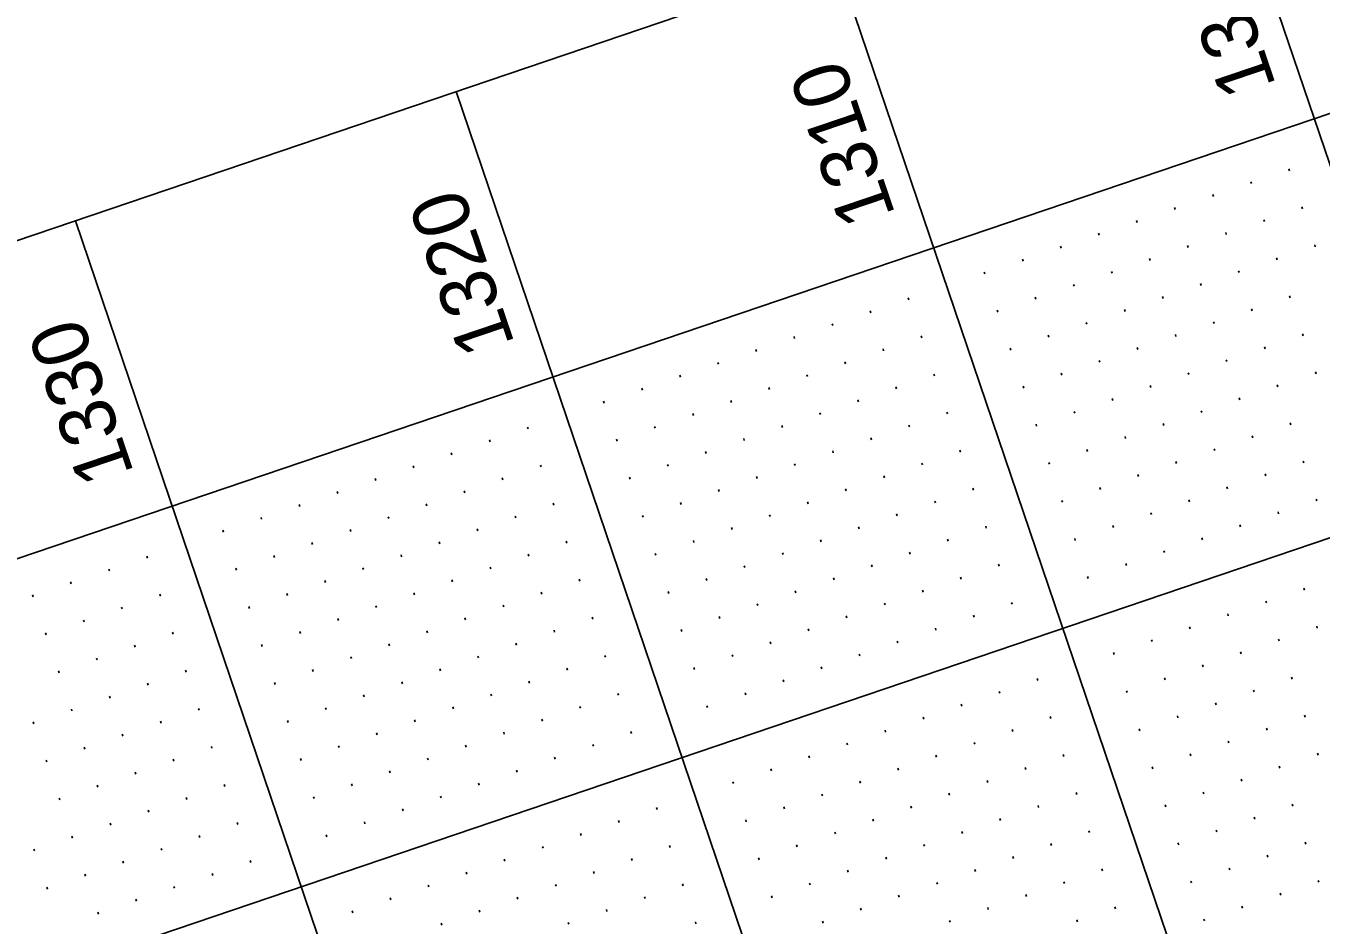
# Model space of a CAD drawing. Extents: x 2150800 to 2152547, y 141860 to 143950.
# Drawn here: x 2151517.9 to 2151679, y 143674.4 to 143786.3 of the extents above; entities that cross this region are included whole.
import ezdxf

# ---------------------------------------------------------------- set-up
doc = ezdxf.new("R2010")
doc.units = 0
for name, color, linetype in [('SHT_Plan_Profile_Sheet_Elev_Txt', 7, 'Continuous'), ('SHT_Profile_Grid_Major', 7, 'Continuous'), ('SHT_Profile_Grid_Minor', 7, 'Continuous'), ('SHT_Sheet_Border', 7, 'Continuous')]:
    doc.layers.add(name, color=color, linetype=linetype)

msp = doc.modelspace()

# ---------------------------------------------------------------- linework, layer by layer
at = {"layer": 'SHT_Profile_Grid_Major'}
for p, q in [((2152172.11, 142318.73), (2151666.12, 143810.24)), ((2152124.76, 142302.67), (2151618.77, 143794.18)), ((2152077.41, 142286.61), (2151571.42, 143778.12)), ((2152030.06, 142270.54), (2151524.07, 143762.05)), ((2151788.93, 143759.51), (2151452.75, 143645.46))]:
    msp.add_line(p, q, dxfattribs=at)
at = {"layer": 'SHT_Profile_Grid_Minor'}
for p, q in [((2151675.08, 143768.27), (2151675, 143768.51)), ((2151670.34, 143766.66), (2151670.26, 143766.9)), ((2151665.61, 143765.06), (2151665.53, 143765.29)), ((2151660.87, 143763.45), (2151660.79, 143763.69)), ((2151676.69, 143763.54), (2151676.61, 143763.77)), ((2151656.14, 143761.84), (2151656.06, 143762.08)), ((2151671.95, 143761.93), (2151671.87, 143762.17)), ((2151651.41, 143760.24), (2151651.32, 143760.48)), ((2151667.22, 143760.32), (2151667.14, 143760.56)), ((2151646.67, 143758.63), (2151646.59, 143758.87)), ((2151662.48, 143758.72), (2151662.4, 143758.95)), ((2151678.29, 143758.8), (2151678.21, 143759.04)), ((2151641.94, 143757.03), (2151641.85, 143757.26)), ((2151657.75, 143757.11), (2151657.67, 143757.35)), ((2151673.56, 143757.19), (2151673.48, 143757.43)), ((2151637.2, 143755.42), (2151637.12, 143755.66)), ((2151653.01, 143755.5), (2151652.93, 143755.74)), ((2151668.82, 143755.59), (2151668.74, 143755.82)), ((2151648.28, 143753.9), (2151648.2, 143754.13)), ((2151664.09, 143753.98), (2151664.01, 143754.22)), ((2151627.73, 143752.21), (2151627.65, 143752.44)), ((2151643.54, 143752.29), (2151643.46, 143752.53)), ((2151659.35, 143752.38), (2151659.27, 143752.61)), ((2151675.16, 143752.46), (2151675.08, 143752.7)), ((2151623, 143750.6), (2151622.92, 143750.84)), ((2151638.81, 143750.68), (2151638.73, 143750.92)), ((2151654.62, 143750.77), (2151654.54, 143751.01)), ((2151670.43, 143750.85), (2151670.35, 143751.09)), ((2151618.26, 143748.99), (2151618.18, 143749.23)), ((2151649.88, 143749.16), (2151649.8, 143749.4)), ((2151665.69, 143749.25), (2151665.61, 143749.48)), ((2151613.53, 143747.39), (2151613.45, 143747.62)), ((2151629.34, 143747.47), (2151629.26, 143747.71)), ((2151645.15, 143747.56), (2151645.07, 143747.79)), ((2151660.96, 143747.64), (2151660.88, 143747.88)), ((2151676.77, 143747.72), (2151676.69, 143747.96)), ((2151608.79, 143745.78), (2151608.71, 143746.02)), ((2151624.6, 143745.87), (2151624.52, 143746.1)), ((2151640.41, 143745.95), (2151640.33, 143746.19)), ((2151656.22, 143746.03), (2151656.14, 143746.27)), ((2151672.04, 143746.12), (2151671.95, 143746.35)), ((2151604.06, 143744.18), (2151603.98, 143744.41)), ((2151619.87, 143744.26), (2151619.79, 143744.5)), ((2151651.49, 143744.43), (2151651.41, 143744.66)), ((2151667.3, 143744.51), (2151667.22, 143744.75)), ((2151599.32, 143742.57), (2151599.24, 143742.81)), ((2151615.13, 143742.65), (2151615.05, 143742.89)), ((2151630.94, 143742.74), (2151630.86, 143742.97)), ((2151646.75, 143742.82), (2151646.67, 143743.06)), ((2151662.57, 143742.91), (2151662.48, 143743.14)), ((2151678.38, 143742.99), (2151678.3, 143743.23)), ((2151594.59, 143740.96), (2151594.51, 143741.2)), ((2151610.4, 143741.05), (2151610.32, 143741.28)), ((2151626.21, 143741.13), (2151626.13, 143741.37)), ((2151642.02, 143741.21), (2151641.94, 143741.45)), ((2151657.83, 143741.3), (2151657.75, 143741.54)), ((2151673.64, 143741.38), (2151673.56, 143741.62)), ((2151589.85, 143739.36), (2151589.77, 143739.59)), ((2151605.66, 143739.44), (2151605.58, 143739.68)), ((2151621.47, 143739.52), (2151621.39, 143739.76)), ((2151653.1, 143739.69), (2151653.02, 143739.93)), ((2151668.91, 143739.78), (2151668.83, 143740.01)), ((2151600.93, 143737.83), (2151600.85, 143738.07)), ((2151616.74, 143737.92), (2151616.66, 143738.15)), ((2151632.55, 143738), (2151632.47, 143738.24)), ((2151648.36, 143738.09), (2151648.28, 143738.32)), ((2151664.17, 143738.17), (2151664.09, 143738.41)), ((2151580.38, 143736.14), (2151580.3, 143736.38)), ((2151596.19, 143736.23), (2151596.11, 143736.46)), ((2151612, 143736.31), (2151611.92, 143736.55)), ((2151627.81, 143736.4), (2151627.73, 143736.63)), ((2151643.63, 143736.48), (2151643.55, 143736.72)), ((2151659.44, 143736.56), (2151659.36, 143736.8)), ((2151675.25, 143736.65), (2151675.17, 143736.88)), ((2151575.65, 143734.54), (2151575.57, 143734.77)), ((2151591.46, 143734.62), (2151591.38, 143734.86)), ((2151607.27, 143734.71), (2151607.19, 143734.94)), ((2151623.08, 143734.79), (2151623, 143735.03)), ((2151654.7, 143734.96), (2151654.62, 143735.19)), ((2151670.51, 143735.04), (2151670.43, 143735.28)), ((2151570.91, 143732.93), (2151570.83, 143733.17)), ((2151602.53, 143733.1), (2151602.45, 143733.34)), ((2151618.34, 143733.18), (2151618.26, 143733.42)), ((2151634.16, 143733.27), (2151634.08, 143733.5)), ((2151649.97, 143733.35), (2151649.89, 143733.59)), ((2151665.78, 143733.44), (2151665.7, 143733.67)), ((2151566.18, 143731.32), (2151566.1, 143731.56)), ((2151581.99, 143731.41), (2151581.91, 143731.65)), ((2151597.8, 143731.49), (2151597.72, 143731.73)), ((2151613.61, 143731.58), (2151613.53, 143731.81)), ((2151629.42, 143731.66), (2151629.34, 143731.9)), ((2151645.23, 143731.74), (2151645.15, 143731.98)), ((2151661.04, 143731.83), (2151660.96, 143732.07)), ((2151676.85, 143731.91), (2151676.77, 143732.15)), ((2151561.44, 143729.72), (2151561.36, 143729.96)), ((2151577.25, 143729.8), (2151577.17, 143730.04)), ((2151593.06, 143729.89), (2151592.98, 143730.12)), ((2151608.87, 143729.97), (2151608.79, 143730.21)), ((2151624.69, 143730.05), (2151624.61, 143730.29)), ((2151656.31, 143730.22), (2151656.23, 143730.46)), ((2151672.12, 143730.31), (2151672.04, 143730.54)), ((2151556.71, 143728.11), (2151556.63, 143728.35)), ((2151572.52, 143728.2), (2151572.44, 143728.43)), ((2151604.14, 143728.36), (2151604.06, 143728.6)), ((2151619.95, 143728.45), (2151619.87, 143728.69)), ((2151635.76, 143728.53), (2151635.68, 143728.77)), ((2151651.57, 143728.62), (2151651.49, 143728.85)), ((2151667.38, 143728.7), (2151667.3, 143728.94)), ((2151551.97, 143726.51), (2151551.89, 143726.74)), ((2151567.78, 143726.59), (2151567.7, 143726.83)), ((2151583.59, 143726.67), (2151583.51, 143726.91)), ((2151599.4, 143726.76), (2151599.32, 143726.99)), ((2151615.22, 143726.84), (2151615.14, 143727.08)), ((2151631.03, 143726.93), (2151630.95, 143727.16)), ((2151646.84, 143727.01), (2151646.76, 143727.25)), ((2151662.65, 143727.09), (2151662.57, 143727.33)), ((2151678.46, 143727.18), (2151678.38, 143727.41)), ((2151547.24, 143724.9), (2151547.16, 143725.14)), ((2151563.05, 143724.98), (2151562.97, 143725.22)), ((2151578.86, 143725.07), (2151578.78, 143725.3)), ((2151594.67, 143725.15), (2151594.59, 143725.39)), ((2151610.48, 143725.24), (2151610.4, 143725.47)), ((2151626.29, 143725.32), (2151626.21, 143725.56)), ((2151657.91, 143725.49), (2151657.83, 143725.72)), ((2151673.73, 143725.57), (2151673.65, 143725.81)), ((2151542.5, 143723.29), (2151542.42, 143723.53)), ((2151558.31, 143723.38), (2151558.23, 143723.61)), ((2151574.12, 143723.46), (2151574.04, 143723.7)), ((2151605.75, 143723.63), (2151605.67, 143723.87)), ((2151621.56, 143723.71), (2151621.48, 143723.95)), ((2151637.37, 143723.8), (2151637.29, 143724.03)), ((2151653.18, 143723.88), (2151653.1, 143724.12)), ((2151668.99, 143723.97), (2151668.91, 143724.2)), ((2151553.58, 143721.77), (2151553.5, 143722.01)), ((2151569.39, 143721.86), (2151569.31, 143722.09)), ((2151585.2, 143721.94), (2151585.12, 143722.18)), ((2151601.01, 143722.02), (2151600.93, 143722.26)), ((2151616.82, 143722.11), (2151616.74, 143722.34)), ((2151632.63, 143722.19), (2151632.55, 143722.43)), ((2151648.44, 143722.28), (2151648.36, 143722.51)), ((2151664.26, 143722.36), (2151664.18, 143722.6)), ((2151533.03, 143720.08), (2151532.95, 143720.32)), ((2151548.84, 143720.16), (2151548.76, 143720.4)), ((2151564.65, 143720.25), (2151564.57, 143720.49)), ((2151580.46, 143720.33), (2151580.38, 143720.57)), ((2151596.28, 143720.42), (2151596.2, 143720.65)), ((2151612.09, 143720.5), (2151612.01, 143720.74)), ((2151627.9, 143720.58), (2151627.82, 143720.82)), ((2151659.52, 143720.75), (2151659.44, 143720.99)), ((2151528.3, 143718.47), (2151528.22, 143718.71)), ((2151544.11, 143718.56), (2151544.03, 143718.8)), ((2151559.92, 143718.64), (2151559.84, 143718.88)), ((2151575.73, 143718.73), (2151575.65, 143718.96)), ((2151607.35, 143718.89), (2151607.27, 143719.13)), ((2151623.16, 143718.98), (2151623.08, 143719.22)), ((2151638.97, 143719.06), (2151638.89, 143719.3)), ((2151654.79, 143719.15), (2151654.71, 143719.38)), ((2151523.56, 143716.87), (2151523.48, 143717.1)), ((2151555.18, 143717.04), (2151555.1, 143717.27)), ((2151570.99, 143717.12), (2151570.91, 143717.36)), ((2151586.81, 143717.2), (2151586.73, 143717.44)), ((2151602.62, 143717.29), (2151602.54, 143717.52)), ((2151618.43, 143717.37), (2151618.35, 143717.61)), ((2151634.24, 143717.46), (2151634.16, 143717.69)), ((2151650.05, 143717.54), (2151649.97, 143717.78)), ((2151676.94, 143716.1), (2151676.86, 143716.34)), ((2151518.83, 143715.26), (2151518.75, 143715.5)), ((2151534.64, 143715.35), (2151534.56, 143715.58)), ((2151550.45, 143715.43), (2151550.37, 143715.67)), ((2151566.26, 143715.51), (2151566.18, 143715.75)), ((2151582.07, 143715.6), (2151581.99, 143715.83)), ((2151597.88, 143715.68), (2151597.8, 143715.92)), ((2151613.69, 143715.77), (2151613.61, 143716)), ((2151629.5, 143715.85), (2151629.42, 143716.09)), ((2151672.2, 143714.5), (2151672.12, 143714.73)), ((2151529.9, 143713.74), (2151529.82, 143713.98)), ((2151545.71, 143713.82), (2151545.63, 143714.06)), ((2151561.53, 143713.91), (2151561.44, 143714.14)), ((2151577.34, 143713.99), (2151577.26, 143714.23)), ((2151608.96, 143714.16), (2151608.88, 143714.4)), ((2151624.77, 143714.24), (2151624.69, 143714.48)), ((2151640.58, 143714.33), (2151640.5, 143714.56)), ((2151667.47, 143712.89), (2151667.39, 143713.13)), ((2151525.17, 143712.13), (2151525.09, 143712.37)), ((2151556.79, 143712.3), (2151556.71, 143712.54)), ((2151572.6, 143712.39), (2151572.52, 143712.62)), ((2151588.41, 143712.47), (2151588.33, 143712.71)), ((2151604.22, 143712.55), (2151604.14, 143712.79)), ((2151620.03, 143712.64), (2151619.95, 143712.87)), ((2151635.85, 143712.72), (2151635.77, 143712.96)), ((2151662.73, 143711.28), (2151662.65, 143711.52)), ((2151678.54, 143711.37), (2151678.46, 143711.6)), ((2151520.43, 143710.53), (2151520.35, 143710.76)), ((2151536.24, 143710.61), (2151536.16, 143710.85)), ((2151552.06, 143710.69), (2151551.97, 143710.93)), ((2151567.87, 143710.78), (2151567.79, 143711.02)), ((2151583.68, 143710.86), (2151583.6, 143711.1)), ((2151599.49, 143710.95), (2151599.41, 143711.18)), ((2151615.3, 143711.03), (2151615.22, 143711.27)), ((2151631.11, 143711.11), (2151631.03, 143711.35)), ((2151658, 143709.68), (2151657.92, 143709.91)), ((2151673.81, 143709.76), (2151673.73, 143710)), ((2151531.51, 143709), (2151531.43, 143709.24)), ((2151547.32, 143709.09), (2151547.24, 143709.33)), ((2151563.13, 143709.17), (2151563.05, 143709.41)), ((2151578.94, 143709.26), (2151578.86, 143709.49)), ((2151610.56, 143709.42), (2151610.48, 143709.66)), ((2151626.38, 143709.51), (2151626.3, 143709.75)), ((2151653.26, 143708.07), (2151653.18, 143708.31)), ((2151669.07, 143708.15), (2151668.99, 143708.39)), ((2151526.77, 143707.4), (2151526.69, 143707.63)), ((2151558.4, 143707.57), (2151558.32, 143707.8)), ((2151574.21, 143707.65), (2151574.13, 143707.89)), ((2151590.02, 143707.73), (2151589.94, 143707.97)), ((2151605.83, 143707.82), (2151605.75, 143708.05)), ((2151621.64, 143707.9), (2151621.56, 143708.14)), ((2151664.34, 143706.55), (2151664.26, 143706.78)), ((2151522.04, 143705.79), (2151521.96, 143706.03)), ((2151537.85, 143705.88), (2151537.77, 143706.11)), ((2151553.66, 143705.96), (2151553.58, 143706.2)), ((2151569.47, 143706.04), (2151569.39, 143706.28)), ((2151585.28, 143706.13), (2151585.2, 143706.36)), ((2151601.09, 143706.21), (2151601.01, 143706.45)), ((2151616.91, 143706.3), (2151616.83, 143706.53)), ((2151643.79, 143704.86), (2151643.71, 143705.09)), ((2151659.6, 143704.94), (2151659.52, 143705.18)), ((2151675.42, 143705.03), (2151675.34, 143705.26)), ((2151533.12, 143704.27), (2151533.03, 143704.51)), ((2151548.93, 143704.35), (2151548.85, 143704.59)), ((2151564.74, 143704.44), (2151564.66, 143704.67)), ((2151580.55, 143704.52), (2151580.47, 143704.76)), ((2151612.17, 143704.69), (2151612.09, 143704.93)), ((2151639.06, 143703.25), (2151638.98, 143703.49)), ((2151654.87, 143703.34), (2151654.79, 143703.57)), ((2151670.68, 143703.42), (2151670.6, 143703.66)), ((2151528.38, 143702.66), (2151528.3, 143702.9)), ((2151560, 143702.83), (2151559.92, 143703.07)), ((2151575.81, 143702.92), (2151575.73, 143703.15)), ((2151591.63, 143703), (2151591.54, 143703.24)), ((2151607.44, 143703.08), (2151607.36, 143703.32)), ((2151634.32, 143701.64), (2151634.24, 143701.88)), ((2151665.95, 143701.81), (2151665.87, 143702.05)), ((2151523.65, 143701.06), (2151523.57, 143701.29)), ((2151539.46, 143701.14), (2151539.38, 143701.38)), ((2151555.27, 143701.22), (2151555.19, 143701.46)), ((2151571.08, 143701.31), (2151571, 143701.55)), ((2151586.89, 143701.39), (2151586.81, 143701.63)), ((2151602.7, 143701.48), (2151602.62, 143701.71)), ((2151629.59, 143700.04), (2151629.51, 143700.28)), ((2151645.4, 143700.12), (2151645.32, 143700.36)), ((2151661.21, 143700.21), (2151661.13, 143700.44)), ((2151677.02, 143700.29), (2151676.94, 143700.53)), ((2151518.91, 143699.45), (2151518.83, 143699.69)), ((2151534.72, 143699.53), (2151534.64, 143699.77)), ((2151550.53, 143699.62), (2151550.45, 143699.86)), ((2151566.34, 143699.7), (2151566.26, 143699.94)), ((2151582.16, 143699.79), (2151582.07, 143700.02)), ((2151624.85, 143698.43), (2151624.77, 143698.67)), ((2151640.66, 143698.52), (2151640.58, 143698.75)), ((2151656.48, 143698.6), (2151656.4, 143698.84)), ((2151672.29, 143698.68), (2151672.21, 143698.92)), ((2151529.99, 143697.93), (2151529.91, 143698.17)), ((2151561.61, 143698.1), (2151561.53, 143698.33)), ((2151577.42, 143698.18), (2151577.34, 143698.42)), ((2151593.23, 143698.26), (2151593.15, 143698.5)), ((2151620.12, 143696.83), (2151620.04, 143697.06)), ((2151635.93, 143696.91), (2151635.85, 143697.15)), ((2151667.55, 143697.08), (2151667.47, 143697.31)), ((2151525.25, 143696.32), (2151525.17, 143696.56)), ((2151541.06, 143696.41), (2151540.98, 143696.64)), ((2151556.87, 143696.49), (2151556.79, 143696.73)), ((2151572.69, 143696.57), (2151572.6, 143696.81)), ((2151588.5, 143696.66), (2151588.42, 143696.89)), ((2151615.38, 143695.22), (2151615.3, 143695.46)), ((2151631.19, 143695.3), (2151631.11, 143695.54)), ((2151647.01, 143695.39), (2151646.93, 143695.62)), ((2151662.82, 143695.47), (2151662.74, 143695.71)), ((2151678.63, 143695.56), (2151678.55, 143695.79)), ((2151520.52, 143694.72), (2151520.44, 143694.95)), ((2151536.33, 143694.8), (2151536.25, 143695.04)), ((2151552.14, 143694.88), (2151552.06, 143695.12)), ((2151567.95, 143694.97), (2151567.87, 143695.2)), ((2151579.03, 143693.45), (2151578.95, 143693.68)), ((2151583.76, 143695.05), (2151583.68, 143695.29)), ((2151610.65, 143693.61), (2151610.57, 143693.85)), ((2151626.46, 143693.7), (2151626.38, 143693.93)), ((2151642.27, 143693.78), (2151642.19, 143694.02)), ((2151658.08, 143693.87), (2151658, 143694.1)), ((2151673.89, 143693.95), (2151673.81, 143694.19)), ((2151531.59, 143693.19), (2151531.51, 143693.43)), ((2151563.22, 143693.36), (2151563.14, 143693.6)), ((2151574.29, 143691.84), (2151574.21, 143692.08)), ((2151605.91, 143692.01), (2151605.83, 143692.24)), ((2151621.73, 143692.09), (2151621.64, 143692.33)), ((2151637.54, 143692.17), (2151637.46, 143692.41)), ((2151669.16, 143692.34), (2151669.08, 143692.58)), ((2151526.86, 143691.59), (2151526.78, 143691.82)), ((2151542.67, 143691.67), (2151542.59, 143691.91)), ((2151558.48, 143691.76), (2151558.4, 143691.99)), ((2151569.56, 143690.23), (2151569.48, 143690.47)), ((2151616.99, 143690.48), (2151616.91, 143690.72)), ((2151632.8, 143690.57), (2151632.72, 143690.81)), ((2151648.61, 143690.65), (2151648.53, 143690.89)), ((2151664.42, 143690.74), (2151664.34, 143690.97)), ((2151522.12, 143689.98), (2151522.04, 143690.22)), ((2151537.93, 143690.06), (2151537.85, 143690.3)), ((2151553.75, 143690.15), (2151553.67, 143690.39)), ((2151564.82, 143688.63), (2151564.74, 143688.86)), ((2151596.44, 143688.79), (2151596.36, 143689.03)), ((2151612.26, 143688.88), (2151612.17, 143689.12)), ((2151628.07, 143688.96), (2151627.99, 143689.2)), ((2151643.88, 143689.05), (2151643.8, 143689.28)), ((2151659.69, 143689.13), (2151659.61, 143689.37)), ((2151675.5, 143689.21), (2151675.42, 143689.45)), ((2151533.2, 143688.46), (2151533.12, 143688.7)), ((2151560.09, 143687.02), (2151560.01, 143687.26)), ((2151591.71, 143687.19), (2151591.63, 143687.42)), ((2151607.52, 143687.27), (2151607.44, 143687.51)), ((2151623.33, 143687.36), (2151623.25, 143687.59)), ((2151639.14, 143687.44), (2151639.06, 143687.68)), ((2151670.76, 143687.61), (2151670.68, 143687.84)), ((2151528.46, 143686.85), (2151528.38, 143687.09)), ((2151544.28, 143686.94), (2151544.2, 143687.17)), ((2151555.35, 143685.41), (2151555.27, 143685.65)), ((2151586.97, 143685.58), (2151586.89, 143685.82)), ((2151618.6, 143685.75), (2151618.52, 143685.99)), ((2151634.41, 143685.83), (2151634.33, 143686.07)), ((2151650.22, 143685.92), (2151650.14, 143686.15)), ((2151666.03, 143686), (2151665.95, 143686.24)), ((2151523.73, 143685.25), (2151523.65, 143685.48)), ((2151539.54, 143685.33), (2151539.46, 143685.57)), ((2151582.24, 143683.98), (2151582.16, 143684.21)), ((2151598.05, 143684.06), (2151597.97, 143684.3)), ((2151613.86, 143684.14), (2151613.78, 143684.38)), ((2151629.67, 143684.23), (2151629.59, 143684.46)), ((2151645.48, 143684.31), (2151645.4, 143684.55)), ((2151661.3, 143684.4), (2151661.21, 143684.63)), ((2151677.11, 143684.48), (2151677.03, 143684.72)), ((2151518.99, 143683.64), (2151518.91, 143683.88)), ((2151534.81, 143683.72), (2151534.73, 143683.96)), ((2151545.88, 143682.2), (2151545.8, 143682.44)), ((2151577.5, 143682.37), (2151577.42, 143682.61)), ((2151593.32, 143682.45), (2151593.24, 143682.69)), ((2151609.13, 143682.54), (2151609.05, 143682.77)), ((2151624.94, 143682.62), (2151624.86, 143682.86)), ((2151640.75, 143682.71), (2151640.67, 143682.94)), ((2151672.37, 143682.87), (2151672.29, 143683.11)), ((2151530.07, 143682.12), (2151529.99, 143682.35)), ((2151541.15, 143680.59), (2151541.07, 143680.83)), ((2151572.77, 143680.76), (2151572.69, 143681)), ((2151588.58, 143680.85), (2151588.5, 143681.08)), ((2151620.2, 143681.01), (2151620.12, 143681.25)), ((2151636.01, 143681.1), (2151635.93, 143681.34)), ((2151651.83, 143681.18), (2151651.74, 143681.42)), ((2151667.64, 143681.27), (2151667.56, 143681.5)), ((2151525.34, 143680.51), (2151525.26, 143680.75)), ((2151536.41, 143678.99), (2151536.33, 143679.23)), ((2151568.03, 143679.16), (2151567.95, 143679.39)), ((2151583.85, 143679.24), (2151583.77, 143679.48)), ((2151599.66, 143679.32), (2151599.58, 143679.56)), ((2151615.47, 143679.41), (2151615.39, 143679.65)), ((2151631.28, 143679.49), (2151631.2, 143679.73)), ((2151647.09, 143679.58), (2151647.01, 143679.81)), ((2151662.9, 143679.66), (2151662.82, 143679.9)), ((2151678.71, 143679.74), (2151678.63, 143679.98)), ((2151520.6, 143678.9), (2151520.52, 143679.14)), ((2151531.68, 143677.38), (2151531.6, 143677.62)), ((2151563.3, 143677.55), (2151563.22, 143677.79)), ((2151579.11, 143677.63), (2151579.03, 143677.87)), ((2151594.92, 143677.72), (2151594.84, 143677.95)), ((2151610.73, 143677.8), (2151610.65, 143678.04)), ((2151626.54, 143677.89), (2151626.46, 143678.12)), ((2151642.36, 143677.97), (2151642.27, 143678.21)), ((2151673.98, 143678.14), (2151673.9, 143678.37)), ((2151526.94, 143675.78), (2151526.86, 143676.01)), ((2151558.56, 143675.94), (2151558.48, 143676.18)), ((2151574.38, 143676.03), (2151574.3, 143676.26)), ((2151590.19, 143676.11), (2151590.11, 143676.35)), ((2151621.81, 143676.28), (2151621.73, 143676.52)), ((2151637.62, 143676.36), (2151637.54, 143676.6)), ((2151653.43, 143676.45), (2151653.35, 143676.68)), ((2151669.24, 143676.53), (2151669.16, 143676.77)), ((2151569.64, 143674.42), (2151569.56, 143674.66)), ((2151585.45, 143674.51), (2151585.37, 143674.74)), ((2151601.26, 143674.59), (2151601.18, 143674.83)), ((2151617.07, 143674.67), (2151616.99, 143674.91)), ((2151632.89, 143674.76), (2151632.8, 143674.99)), ((2151648.7, 143674.84), (2151648.62, 143675.08)), ((2151664.51, 143674.93), (2151664.43, 143675.16))]:
    msp.add_line(p, q, dxfattribs=at)
at = {"layer": 'SHT_Sheet_Border'}
msp.add_line((2151843.89, 143830.95), (2151394.07, 143678.35), dxfattribs=at)
msp.add_lwpolyline([(2151383.74, 142051.28), (2150877.75, 143542.79), (2151872.09, 143880.12), (2152378.08, 142388.61)], close=True, dxfattribs=at)

# ---------------------------------------------------------------- texts
at = {"layer": 'SHT_Plan_Profile_Sheet_Elev_Txt'}
for s, p in [('1300', (2151673.45, 143778.82)), ('1310', (2151626.1, 143762.76)), ('1320', (2151578.75, 143746.7)), ('1330', (2151531.4, 143730.63))]:
    msp.add_text(s, height=7, rotation=108.7393, dxfattribs=at).set_placement(p)

doc.saveas('drawing.dxf')
